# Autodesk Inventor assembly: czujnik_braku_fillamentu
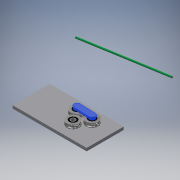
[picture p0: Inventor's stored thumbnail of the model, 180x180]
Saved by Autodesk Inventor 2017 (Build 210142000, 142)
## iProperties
Created: 2021-01
Part Number: czujnik_braku_fillamentu
Document SubType Name: Assembly
Designer: WindowsX
Author: WindowsX
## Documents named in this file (5)
- C:\Users\WindowsX\Desktop\modele_3d\czujnik_braku_fillamentu.iam
- C:\Users\WindowsX\Desktop\modele_3d\rolka_extrudera.iam
- C:\Users\WindowsX\Desktop\modele_3d\podstawa_czujnika.ipt
- C:\Users\WindowsX\Desktop\modele_3d\FILAMENT.ipt
- C:\Users\WindowsX\Desktop\modele_3d\docisk_czujnika.ipt
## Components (6 placed, 4 different names)
1. rolka_extrudera:1 [sub-assembly] — Zestawiający:1
2. podstawa_czujnika:1 — Zestawiający:1, Zestawiający:2, Zestawiający:3
3. rolka_extrudera:2 [sub-assembly] — Zestawiający:3, Zestawiający:6
4. rolka_extrudera:3 [sub-assembly] — Zestawiający:2, Zestawiający:4, Zestawiający:5
5. FILAMENT:1
6. docisk_czujnika:1 — Zestawiający:4, Zestawiający:5, Zestawiający:6
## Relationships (6: Mate 6)
- Zestawiający:1 [Mate]: rolka_extrudera:1 ↔ podstawa_czujnika:1
- Zestawiający:2 [Mate]: podstawa_czujnika:1 ↔ rolka_extrudera:3
- Zestawiający:3 [Mate]: podstawa_czujnika:1 ↔ rolka_extrudera:2
- Zestawiający:4 [Mate]: rolka_extrudera:3 ↔ docisk_czujnika:1
- Zestawiający:5 [Mate]: rolka_extrudera:3 ↔ docisk_czujnika:1
- Zestawiający:6 [Mate]: rolka_extrudera:2 ↔ docisk_czujnika:1
